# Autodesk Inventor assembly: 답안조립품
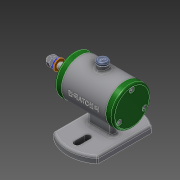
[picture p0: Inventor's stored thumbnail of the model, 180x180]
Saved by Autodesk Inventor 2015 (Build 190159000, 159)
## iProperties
Created: 2017-12
Part Number: 답안조립품
Document SubType Name: Assembly
Designer: SCD-A05
Author: SCD-A05
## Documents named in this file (14)
- D:\471208V1006\답안조립품.iam
- D:\471208V1006\V벨트풀리.ipt
- D:\471208V1006\고무캡.ipt
- D:\471208V1006\너트 M 8.ipt
- D:\471208V1006\뒤커버.ipt
- D:\471208V1006\베어링 15 x 32 x 9.ipt
- D:\471208V1006\본체.ipt
- D:\471208V1006\볼트 M4 x 12.ipt
- D:\471208V1006\스프링와셔 8.ipt
- D:\471208V1006\앞커버.ipt
- D:\471208V1006\오일 실 15 25 7.ipt
- D:\471208V1006\와셔 8x17.ipt
- D:\471208V1006\축.ipt
- D:\471208V1006\키 3 x 3 x 12.ipt
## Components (2 placed, 2 different names)
1. V벨트풀리:1
2. 고무캡:1
